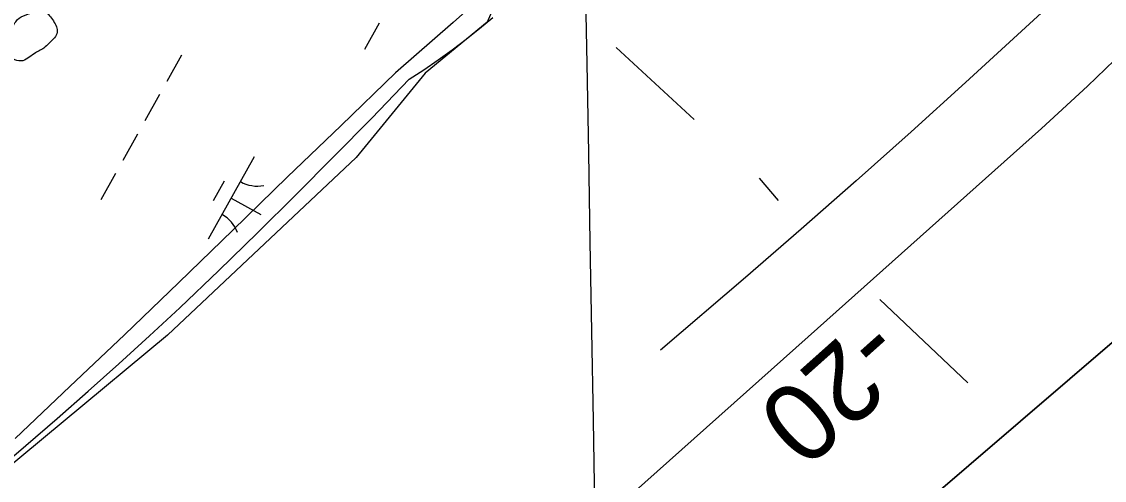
# Model space of a CAD drawing. Extents: x 3923531 to 3943530, y 207391 to 229799.
# Drawn here: x 3930098 to 3930673, y 213804 to 214048 of the extents above; entities that cross this region are included whole.
import ezdxf

# ---------------------------------------------------------------- set-up
doc = ezdxf.new("R2010")
doc.units = 0
for name, color, linetype in [('V-GRID-MAJR', 7, 'Continuous'), ('V-LEVE-OTLN', 7, 'Continuous'), ('V-LEVE-TOET', 7, 'Continuous'), ('V-RIVR-EDGE', 7, 'Continuous'), ('V-RRAP-FSHR', 7, 'Continuous'), ('V-TOPO-DPTH', 7, 'Continuous'), ('V-TOPO-MINR', 7, 'Continuous'), ('V-TOPO-MINR-IDEN', 7, 'Continuous'), ('V-WETL-SWMP', 7, 'Continuous')]:
    doc.layers.add(name, color=color, linetype=linetype)

msp = doc.modelspace()

# ---------------------------------------------------------------- linework, layer by layer
at = {"layer": 'V-GRID-MAJR'}
msp.add_spline([(3930464.51, 210285.11), (3930436.78, 211847.72), (3930329.23, 217907.73), (3930301.12, 219492.06)], degree=3, dxfattribs=at)
at = {"layer": 'V-LEVE-OTLN'}
msp.add_spline([(3930112.63, 214036.5), (3930116.94, 214042.26), (3930114.88, 214048.26), (3930110.5, 214052.97), (3930100.42, 214051.52), (3930095.77, 214048.95), (3930092.41, 214044.06), (3930087.69, 214039.68), (3930087.56, 214036.04), (3930088.75, 214030.99), (3930093.2, 214028.09), (3930097.71, 214027.02), (3930104.68, 214030.86), (3930109.8, 214033.87), (3930112.63, 214036.5)], degree=3, dxfattribs=at)
at = {"layer": 'V-LEVE-TOET'}
for p, q in [((3930454.88, 213995.93), (3930413.56, 214034.18)), ((3930499.68, 213952.92), (3930489.57, 213964.84)), ((3930600.19, 213856.14), (3930553.43, 213900.36))]:
    msp.add_line(p, q, dxfattribs=at)
at = {"layer": 'V-RIVR-EDGE'}
msp.add_lwpolyline([(3930578.51, 214437.75), (3930545.51, 214372.92), (3930534.9, 214328.13), (3930541.97, 214312.81), (3930556.12, 214285.7), (3930559.65, 214264.48), (3930523.11, 214217.33), (3930420.57, 214115.96), (3930382.85, 214088.85), (3930360.45, 214082.96), (3930345.13, 214047.6), (3930312.12, 214020.48), (3930275.58, 213975.69), (3930175.39, 213881.4), (3930064.59, 213789.46)], dxfattribs=at)
at = {"layer": 'V-RRAP-FSHR'}
msp.add_lwpolyline([(3930652.61, 214441.15), (3930638.61, 214403.7), (3930623.71, 214366.58), (3930608.49, 214329.58), (3930585.29, 214297.42), (3930557.39, 214268.38), (3930529.53, 214239.68), (3930501.68, 214210.97), (3930472.89, 214183.21), (3930443.93, 214155.62), (3930414.96, 214128.33), (3930386, 214100.45), (3930356.31, 214073.65), (3930326.97, 214047.44), (3930296.42, 214020.64), (3930267.67, 213992.83), (3930238.92, 213965.26), (3930210.16, 213937.22), (3930181.41, 213909.42), (3930152.56, 213881.7), (3930123.58, 213854.13), (3930094.6, 213826.57)], dxfattribs=at)
at = {"layer": 'V-TOPO-DPTH'}
for points in [[(3930083.42, 213409.58), (3930101.58, 213423.44), (3930119.97, 213437.02), (3930138.39, 213450.55), (3930156.86, 213464.01), (3930175.36, 213477.42), (3930268.66, 213544.79), (3930333.21, 213592.66), (3930396.91, 213641.59), (3930459.36, 213692.13), (3930520.96, 213743.73), (3930707.8, 213904.31), (3930737.43, 213930.07), (3930766.87, 213956.05), (3930796.02, 213982.36), (3930824.98, 214008.89), (3931395.67, 214639.33)], [(3930083.42, 213409.58), (3930101.58, 213423.44), (3930119.97, 213437.02), (3930138.39, 213450.55), (3930156.86, 213464.01), (3930175.36, 213477.42), (3930268.66, 213544.79), (3930333.21, 213592.66), (3930396.91, 213641.59), (3930459.36, 213692.13), (3930520.96, 213743.73), (3930707.8, 213904.31), (3930737.43, 213930.07), (3930766.87, 213956.05), (3930796.02, 213982.36), (3930824.98, 214008.89), (3931395.67, 214639.33)], [(3930996.63, 214375.9), (3930733.34, 214084.71), (3930710.68, 214060.43), (3930687.52, 214036.67), (3930663.6, 214013.65), (3930639.19, 213991.14), (3930515.4, 213880.63), (3930428.72, 213803.24), (3930342.04, 213725.84), (3930255.37, 213648.43), (3930168.71, 213571.02), (3929986.55, 213408.3), (3929957.01, 213381.85), (3929927.52, 213355.35), (3929898.09, 213328.78), (3929868.7, 213302.16), (3929857.71, 213292.18), (3929822.64, 213260.78), (3929787.28, 213229.73), (3929751.47, 213199.19), (3929715.37, 213168.98), (3929345.89, 212722.35)]]:
    msp.add_lwpolyline(points, dxfattribs=at)
at = {"layer": 'V-TOPO-MINR'}
for points in [[(3931247.3, 214814.92), (3930817, 214260.62), (3930799.58, 214235.42), (3930781.44, 214210.79), (3930762.21, 214187), (3930742.25, 214163.76), (3930670.06, 214083.42), (3930663.15, 214075.95), (3930656.09, 214068.61), (3930648.83, 214061.49), (3930641.42, 214054.51), (3930598.91, 214015.59), (3930570.01, 213989.4), (3930540.94, 213963.4), (3930511.63, 213937.68), (3930482.14, 213912.15), (3930437, 213873.46)], [(3931395.67, 214639.33), (3930824.98, 214008.89), (3930796.02, 213982.36), (3930766.87, 213956.05), (3930737.43, 213930.07), (3930707.8, 213904.31), (3930520.96, 213743.73), (3930459.36, 213692.13), (3930396.91, 213641.59), (3930333.21, 213592.66), (3930268.66, 213544.79), (3930175.36, 213477.42), (3930156.86, 213464.01), (3930138.39, 213450.55), (3930119.97, 213437.02), (3930101.58, 213423.44), (3930083.42, 213409.58)], [(3930996.63, 214375.9), (3930733.34, 214084.71), (3930710.68, 214060.43), (3930687.52, 214036.67), (3930663.6, 214013.65), (3930639.19, 213991.14), (3930515.4, 213880.63), (3930428.72, 213803.24), (3930342.04, 213725.84), (3930255.37, 213648.43), (3930168.71, 213571.02), (3929986.55, 213408.3), (3929957.01, 213381.85), (3929927.52, 213355.35), (3929898.09, 213328.78), (3929868.7, 213302.16), (3929857.71, 213292.18), (3929822.64, 213260.78), (3929787.28, 213229.73), (3929751.47, 213199.19), (3929715.37, 213168.98)]]:
    msp.add_lwpolyline(points, dxfattribs=at)
at = {"layer": 'V-WETL-SWMP'}
for p, q in [((3930341.07, 214044.27), (3930348.14, 214050.17)), ((3930287.77, 214047.15), (3930279.97, 214033.19)), ((3930333.86, 214038.53), (3930341.07, 214044.27)), ((3930326.52, 214032.97), (3930333.86, 214038.53)), ((3930319.05, 214027.57), (3930326.52, 214032.97)), ((3930182.9, 214030.14), (3930175.1, 214016.17)), ((3930311.46, 214022.35), (3930319.05, 214027.57)), ((3930303.74, 214017.31), (3930311.46, 214022.35)), ((3930283.81, 213996.73), (3930303.74, 214017.31)), ((3930171.2, 214009.19), (3930163.39, 213995.22)), ((3930263.73, 213976.29), (3930283.81, 213996.73)), ((3930159.49, 213988.23), (3930151.69, 213974.27)), ((3930221.45, 213976.05), (3930197.07, 213932.4)), ((3930243.51, 213956), (3930263.73, 213976.29)), ((3930147.79, 213967.28), (3930139.98, 213953.31)), ((3930205.45, 213963.22), (3930199.6, 213952.75)), ((3930209.26, 213954.22), (3930224.97, 213945.44)), ((3930223.13, 213935.86), (3930243.51, 213956)), ((3930202.61, 213915.87), (3930223.13, 213935.86)), ((3930181.94, 213896.02), (3930202.61, 213915.87)), ((3930165.87, 213881.08), (3930181.94, 213896.02)), ((3930149.66, 213866.29), (3930165.87, 213881.08)), ((3930133.31, 213851.64), (3930149.66, 213866.29)), ((3930116.83, 213837.15), (3930133.31, 213851.64)), ((3930100.22, 213822.81), (3930116.83, 213837.15)), ((3930083.47, 213808.62), (3930100.22, 213822.81))]:
    msp.add_line(p, q, dxfattribs=at)
for centre, start, end in [((3930222.94, 213978.22), 240.03808, 281.58174), ((3930196, 213929.99), 20.03808, 61.58174)]:
    msp.add_arc(centre, 17.62, start, end, dxfattribs=at)

# ---------------------------------------------------------------- texts
at = {"layer": 'V-TOPO-MINR-IDEN'}
msp.add_text('-20', height=41.5, rotation=221.7596, dxfattribs=at).set_placement((3930545.86, 213893.92))

doc.saveas('drawing.dxf')
